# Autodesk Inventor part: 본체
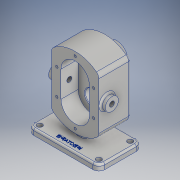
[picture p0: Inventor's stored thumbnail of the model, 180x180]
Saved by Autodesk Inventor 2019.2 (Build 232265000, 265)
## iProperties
Created: 2019-03
Part Number: 본체
Material: 알루미늄 6061
Document SubType Name: Modeling
Designer: User
Density: 2.7 g/cm^3
Appearance: 알루미늄 - 평지
Mass: 1187.13 g
Surface Area: 719.679 cm^2
Volume: 439.678 cm^3
Author: User
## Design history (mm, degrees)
sketch "스케치1"
  geometry: L1 (-36.5, 60)-(36.5, 60); L2 (36.5, 60)-(36.5, -60); L3 (36.5, -60)-(-36.5, -60); L4 (-36.5, -60)-(-36.5, 60); L5 (-51.1, 0)-(51.1, 0) reference; L6 (0, -84)-(0, 84) reference; 1 further point
  constraints: 8 end point, 2 parallel, 1 horizontal, 1 perpendicular
  dimensions: "d0" = 73 distance of L2.end L3.end; "d1" = 120 distance of L1.end L2.end; "d2" = 60 distance between parallel lines of L5 L1; "d3" = 36.5 distance between parallel lines of L6 L2
extrude "돌출1" new body sketch "스케치1" distance "d4" = 10; taper "d5" = 0 deg
fillet "모깎기1" dims "d6" = 10
sketch "스케치2"
  geometry: A1 r 10 centre (26.5, -50) between (26.5, -60) and (36.5, -50) reference; A2 r 10 centre (26.5, 50) between (36.5, 50) and (26.5, 60) reference; A3 r 10 centre (-26.5, 50) between (-26.5, 60) and (-36.5, 50) reference; A4 r 10 centre (-26.5, -50) between (-36.5, -50) and (-26.5, -60) reference; 5 further points
  constraints: 4 coincident
hole "구멍1" sketch "스케치2" at (26.5, -50), (26.5, 50), (-26.5, 50), (-26.5, -50) diameter "d7" = 9; stored, may be unused: countersink angle "d11" = 90 deg, drill point angle "d13" = 118 deg; dims "d8" = 18, "d9" = 4, "d10" = 2, "d12" = 22
fillet "모깎기2" dims "d14" = 3
sketch "스케치5"
  geometry: 1 further point
sketch "스케치6"
  geometry: L1 (-3.096, 78)-(103.096, 78); L2 (-34, 0)-(134, 0) reference; L3 (10, 33.279)-(10, 122.721); L4 (90, 122.721)-(90, 33.279); L5 (90, 8.392)-(10, 147.608); L6 (10, 8.392)-(90, 147.608); L7 (50, -29.522)-(50, 177.129) reference; A1 r 60 centre (50, 78) between (10, 33.279) and (90, 33.279); A2 r 60 centre (50, 78) between (90, 122.721) and (10, 122.721); 1 further point
  constraints: 10 end point, 4 point on circle, 3 midpoint, 2 centre point, 1 horizontal, 1 parallel
  dimensions: "d24" = 78 distance between parallel lines of L2 L1; "d27" = 80 distance of L4.start L3.end; "d68" = 40 distance between parallel lines of L3 L7; "d69" = 40 distance between parallel lines of L4 L7; "d70" = 60 radius of A2; "d71" = 60 radius of A1
extrude "돌출2" join sketch "스케치6" distance "d28" = 53; taper "d29" = 0 deg
sketch "스케치7"
  geometry: L1 (36.5, 0)-(26.5, 0) reference; L2 (36.5, 0)-(-6.5, 0); L3 (-6.5, 0)-(-6.5, 27.707); L4 (-6.5, 27.707)-(36.5, 27.707); L5 (36.5, 27.707)-(36.5, 0); 1 further point
  constraints: 8 end point, 2 parallel, 1 horizontal, 1 perpendicular
  dimensions: "d30" = 43 distance between parallel lines of L5 L3
extrude "돌출3" join sketch "스케치7" stored distance "d31" = 12; taper "d32" = 0 deg
fillet "모깎기3" dims "d33" = 10
sketch "스케치8"
  geometry: L1 (-152.214, 78)-(34.212, 78); L2 (0, 0)-(-100, 0) reference; L3 (-82.648, 100)-(-21.624, 100); L4 (-82.648, 56)-(-21.624, 56); L5 (-74, 100)-(-74, 56); L6 (-26, 100)-(-26, 56); A1 r 24 centre (-50, 100) between (-26, 100) and (-74, 100); A2 r 24 centre (-50, 56) between (-74, 56) and (-26, 56); 1 further point
  constraints: 10 end point, 6 point on line, 4 point on circle, 2 centre point, 2 horizontal, 2 symmetric about line
  dimensions: "d34" = 78 distance between parallel lines of L2 L1; "d35" = 22 distance between parallel lines of L1 L3; "d36" = 48 diameter of A1; "d37" = 48 diameter of A2
extrude "돌출4" cut sketch "스케치8" distance "d38" = 29; taper "d39" = 0 deg
sketch "스케치9"
  geometry: L1 (-140.527, 78)-(33.666, 78); L2 (0, 0)-(-100, 0) reference; C1 r 12.5 at (-50, 100); C2 r 12.5 at (-50, 56); 1 further point
  constraints: 2 centre point, 2 end point, 1 horizontal
  dimensions: "d40" = 25 diameter of C1; "d41" = 78 distance between parallel lines of L2 L1; "d42" = 25 diameter of C2; "d43" = 22 distance from line of L1 C2.centre; "d44" = 22 distance from line of L1 C1.centre
extrude "돌출5" cut sketch "스케치9" distance "d45" = 15; taper "d46" = 0 deg
sketch "스케치11"
  geometry: L1 (-34, 0)-(134, 0) reference; C1 r 19 at (50, 100); 1 further point
  constraints: 1 centre point
  dimensions: "d48" = 100 distance from line of L1 C1.centre; "d49" = 38 diameter of C1
extrude "돌출6" join sketch "스케치11" distance "d50" = 17; taper "d51" = 0 deg
sketch "스케치12"
  geometry: C1 r 19 at (0, 0) reference; 2 further points
  constraints: 1 coincident
hole "구멍2" sketch "스케치12" at (0, 0) diameter "d52" = 17; stored, may be unused: countersink angle "d56" = 90 deg, drill point angle "d58" = 118 deg; dims "d53" = 18, "d54" = 28, "d55" = 7.3, "d57" = 22
sketch "스케치14"
  geometry: L1 (-87.6, -38)-(14.6, -38) reference; L2 (-53, 0)-(-53, 80) reference; C1 r 11 at (-39, 40); 1 further point
  constraints: 1 centre point
  dimensions: "d63" = 22 diameter of C1; "d64" = 78 distance from line of C1.centre L1; "d65" = 14 distance from line of C1.centre L2
extrude "돌출7" join sketch "스케치14" distance "d66" = 8; taper "d67" = 0 deg
sketch "스케치13"
  geometry: L1 (0, 0)-(-100, 0) reference; L2 (-110.295, 78)-(9.201, 78); C1 r 12.5 at (-50, 56) reference; A1 r 31 centre (-50, 56) between (-81, 56) and (-19, 56); A2 r 31 centre (-50, 100) between (-81, 100) and (-19, 100); 3 further points
  constraints: 4 point on circle, 2 centre point, 2 end point, 1 concentric, 1 horizontal, 1 symmetric about line, 1 other
  dimensions: "d72" = 106 distance of point (-50, 25) point (-50, 131); "d73" = 78 distance between parallel lines of L1 L2; "d74" = 53 distance from line of L2 point (-50, 131); "d75" = 62 diameter of A1
hole "구멍3" sketch "스케치13" at (-81, 100), (-50, 131), (-19, 100), (-19, 56), (-81, 56), (-50, 25) diameter "d76" = 4.134; stored, may be unused: countersink angle "d80" = 90 deg, drill point angle "d82" = 118 deg; dims "d77" = 10, "d78" = 4, "d79" = 2, "d81" = 12
sketch "스케치15"
  geometry: C1 r 11 at (0, 0) reference; 2 further points
  constraints: 1 coincident
hole "구멍4" sketch "스케치15" at (0, 0) diameter "d83" = 8.376; stored, may be unused: countersink angle "d87" = 90 deg, drill point angle "d89" = 118 deg; dims "d84" = 100, "d85" = 4, "d86" = 2, "d88" = 12
sketch "스케치16"
  geometry: L1 (26.5, 60)-(-26.5, 60) reference; L2 (-36.5, 50)-(-36.5, -50) reference; 2 further points
  constraints: 1 other
  dimensions: "d90" = 60 distance from line of point (-26.5, 0) L1; "d91" = 10 distance from line of L2 point (-26.5, 0)
feature "엠보싱1" sketch "스케치16" dims "d0" = 73, "d1" = 120, "d2" = 60, "d3" = 36.5, "d92" = 0.5, "d93" = 0
fillet "모깎기4" dims "d94" = 3
chamfer "모따기1" distance "d95" = 1; stored, may be unused: second distance "d96" = 2, angle "d97" = 45 deg
fillet "모깎기5" dims "d101" = 0.5
fillet "모깎기6" dims "d102" = 3
fillet "모깎기7" dims "d103" = 3
fillet "모깎기8" dims "d104" = 3
fillet "모깎기9" dims "d105" = 3
fillet "모깎기10" dims "d106" = 3
sketch "스케치17"
  geometry: L1 (-31.7, 100)-(115.473, 100); L2 (36.5, 0)-(26.5, 0) reference; L3 (53.5, 114.404)-(52.8, 114); L4 (52.8, 114)-(52.8, 100); L5 (53.5, 114)-(53.5, 86) reference; L6 (53.5, 114.404)-(53.5, 100); L7 (52.8, 100)-(53.5, 100); L8 (46.7, 114)-(53.5, 114) reference; 1 further point
  constraints: 10 end point, 3 point on line, 1 horizontal, 1 midpoint, 1 perpendicular
  dimensions: "d114" = 100 distance between parallel lines of L2 L1; "d115" = 0.7 distance from line of L5 L4.end; "d116" = 30 deg angle of L1 L3
revolve "회전1" sketch "스케치17" stored, may be unused: angle "d117" = 90 deg
node "솔리드1"
mirror "미러1"
